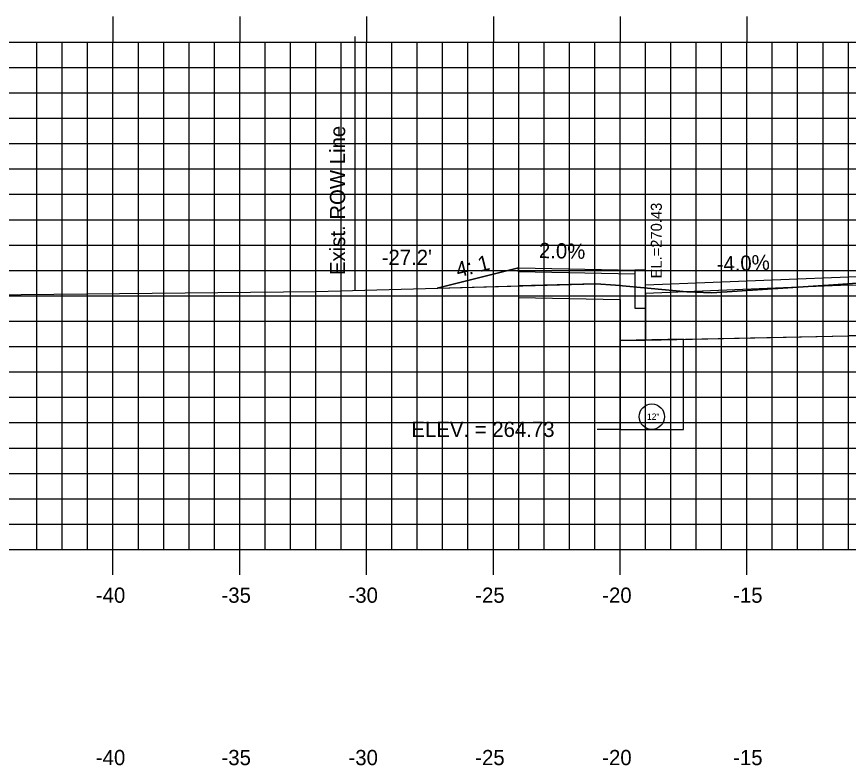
# Model space of a CAD drawing. Extents: x 854899 to 855069, y 366268 to 366378.
# Drawn here: x 854937.97 to 854970.77, y 366298.73 to 366328.24 of the extents above; entities that cross this region are included whole.
import ezdxf

# ---------------------------------------------------------------- set-up
doc = ezdxf.new("R2010")
doc.units = 0
for name, color, linetype in [('ANNOTATION', 7, 'Continuous'), ('D_Curb_Type_1_Lt', 7, 'Continuous'), ('D_Roadway_Centerline', 7, 'Continuous'), ('D_Roadway_Edge_Shoulder', 7, 'Continuous'), ('D_Roadway_FinishedGrade', 7, 'Continuous'), ('D_Roadway_Sidewalks_Paved', 7, 'Continuous'), ('D_Roadway_SubGrade', 7, 'Continuous'), ('D_Text_Standard', 7, 'Continuous'), ('E_ROW_Line', 7, 'Continuous'), ('H_V ANNOTATION', 7, 'Continuous'), ('JUNK COM EXC', 7, 'Continuous'), ('JUNK FILL', 7, 'Continuous'), ('junk strct exc', 7, 'Continuous'), ('MAJOR', 7, 'Continuous'), ('MINOR', 7, 'Continuous'), ('PDRAIN', 7, 'Continuous'), ('S_Roadway_Centerline', 7, 'Continuous')]:
    doc.layers.add(name, color=color, linetype=linetype)

msp = doc.modelspace()

# ---------------------------------------------------------------- linework, layer by layer
at = {"layer": 'D_Curb_Type_1_Lt'}
msp.add_lwpolyline([(854962.357, 366318.249), (854962.357, 366316.749), (854962.774, 366316.749), (854962.774, 366318.249)], close=True, dxfattribs=at)
at = {"layer": 'D_Roadway_Centerline'}
msp.add_lwpolyline([(854970.774, 366317.986), (854981.774, 366318.206), (854992.774, 366317.986)], dxfattribs=at)
at = {"layer": 'D_Roadway_Edge_Shoulder'}
msp.add_lwpolyline([(854962.774, 366317.666), (854970.774, 366317.986), (854981.774, 366318.206), (854992.774, 366317.986), (855000.774, 366317.665)], dxfattribs=at)
at = {"layer": 'D_Roadway_FinishedGrade'}
msp.add_line((854954.559, 366317.538), (854957.769, 366318.341), dxfattribs=at)
at = {"layer": 'D_Roadway_Sidewalks_Paved'}
msp.add_lwpolyline([(854957.769, 366318.341), (854962.357, 366318.249), (854962.357, 366318.082), (854957.769, 366318.174)], close=True, dxfattribs=at)
at = {"layer": 'D_Roadway_SubGrade'}
msp.add_lwpolyline([(854957.769, 366318.174), (854957.769, 366317.174), (854961.774, 366317.094), (854961.774, 366315.472), (854962.774, 366315.492)], dxfattribs=at)
for points in [[(854970.774, 366317.652), (854962.774, 366317.332), (854962.774, 366315.492), (854970.774, 366315.652)], [(854970.774, 366315.652), (854970.774, 366317.652), (854981.774, 366317.872), (854992.774, 366317.652), (854992.774, 366315.652), (854981.774, 366315.872)]]:
    msp.add_lwpolyline(points, close=True, dxfattribs=at)
at = {"layer": 'D_Text_Standard'}
msp.add_lwpolyline([(854961.774, 366311.971), (854961.543, 366311.971), (854960.863, 366311.971)], dxfattribs=at)
at = {"layer": 'E_ROW_Line'}
msp.add_line((854951.329, 366317.451), (854951.329, 366327.451), dxfattribs=at)
at = {"layer": 'JUNK COM EXC'}
msp.add_lwpolyline([(854971.488, 366317.76), (854970.188, 366317.674), (854965.385, 366317.346), (854964.403, 366317.388), (854961.589, 366317.66), (854960.814, 366317.707), (854957.769, 366317.625), (854957.769, 366317.174), (854961.774, 366317.094), (854961.774, 366315.472), (854970.774, 366315.652), (854981.774, 366315.872)], dxfattribs=at)
at = {"layer": 'JUNK FILL'}
msp.add_lwpolyline([(854957.774, 366317.625), (854957.774, 366318.341), (854957.769, 366318.341), (854954.559, 366317.538)], close=True, dxfattribs=at)
at = {"layer": 'junk strct exc'}
msp.add_lwpolyline([(854961.774, 366315.472), (854961.774, 366311.971), (854964.274, 366311.971), (854964.274, 366315.522)], close=True, dxfattribs=at)
at = {"layer": 'MAJOR'}
for p, q in [((854941.774, 366328.238), (854941.774, 366327.236)), ((854946.774, 366328.238), (854946.774, 366327.236)), ((854951.774, 366328.238), (854951.774, 366327.236)), ((854956.774, 366328.238), (854956.774, 366327.236)), ((854961.774, 366328.238), (854961.774, 366327.236)), ((854966.774, 366328.238), (854966.774, 366327.236)), ((854911.774, 366327.236), (855051.774, 366327.236)), ((854911.774, 366327.236), (855051.774, 366327.236)), ((854941.774, 366307.236), (854941.774, 366327.236)), ((854946.774, 366307.236), (854946.774, 366327.236)), ((854951.774, 366307.236), (854951.774, 366327.236)), ((854956.774, 366307.236), (854956.774, 366327.236)), ((854961.774, 366307.236), (854961.774, 366327.236)), ((854966.774, 366307.236), (854966.774, 366327.236)), ((854911.774, 366322.236), (855051.774, 366322.236)), ((854911.774, 366317.236), (855051.774, 366317.236)), ((854911.774, 366312.236), (855051.774, 366312.236)), ((854911.774, 366307.236), (855051.774, 366307.236)), ((854911.774, 366307.236), (855051.774, 366307.236)), ((854941.774, 366306.234), (854941.774, 366307.236)), ((854946.774, 366306.234), (854946.774, 366307.236)), ((854951.774, 366306.234), (854951.774, 366307.236)), ((854956.774, 366306.234), (854956.774, 366307.236)), ((854961.774, 366306.234), (854961.774, 366307.236)), ((854966.774, 366306.234), (854966.774, 366307.236))]:
    msp.add_line(p, q, dxfattribs=at)
at = {"layer": 'MINOR'}
for p, q in [((854938.774, 366307.236), (854938.774, 366327.236)), ((854939.774, 366307.236), (854939.774, 366327.236)), ((854940.774, 366307.236), (854940.774, 366327.236)), ((854942.774, 366307.236), (854942.774, 366327.236)), ((854943.774, 366307.236), (854943.774, 366327.236)), ((854944.774, 366307.236), (854944.774, 366327.236)), ((854945.774, 366307.236), (854945.774, 366327.236)), ((854947.774, 366307.236), (854947.774, 366327.236)), ((854948.774, 366307.236), (854948.774, 366327.236)), ((854949.774, 366307.236), (854949.774, 366327.236)), ((854950.774, 366307.236), (854950.774, 366327.236)), ((854952.774, 366307.236), (854952.774, 366327.236)), ((854953.774, 366307.236), (854953.774, 366327.236)), ((854954.774, 366307.236), (854954.774, 366327.236)), ((854955.774, 366307.236), (854955.774, 366327.236)), ((854957.774, 366307.236), (854957.774, 366327.236)), ((854958.774, 366307.236), (854958.774, 366327.236)), ((854959.774, 366307.236), (854959.774, 366327.236)), ((854960.774, 366307.236), (854960.774, 366327.236)), ((854962.774, 366307.236), (854962.774, 366327.236)), ((854963.774, 366307.236), (854963.774, 366327.236)), ((854964.774, 366307.236), (854964.774, 366327.236)), ((854965.774, 366307.236), (854965.774, 366327.236)), ((854967.774, 366307.236), (854967.774, 366327.236)), ((854968.774, 366307.236), (854968.774, 366327.236)), ((854969.774, 366307.236), (854969.774, 366327.236)), ((854970.774, 366307.236), (854970.774, 366327.236)), ((854911.774, 366326.236), (855051.774, 366326.236)), ((854911.774, 366325.236), (855051.774, 366325.236)), ((854911.774, 366324.236), (855051.774, 366324.236)), ((854911.774, 366323.236), (855051.774, 366323.236)), ((854911.774, 366321.236), (855051.774, 366321.236)), ((854911.774, 366320.236), (855051.774, 366320.236)), ((854911.774, 366319.236), (855051.774, 366319.236)), ((854911.774, 366318.236), (855051.774, 366318.236)), ((854911.774, 366316.236), (855051.774, 366316.236)), ((854911.774, 366315.236), (855051.774, 366315.236)), ((854911.774, 366314.236), (855051.774, 366314.236)), ((854911.774, 366313.236), (855051.774, 366313.236)), ((854911.774, 366311.236), (855051.774, 366311.236)), ((854911.774, 366310.236), (855051.774, 366310.236)), ((854911.774, 366309.236), (855051.774, 366309.236)), ((854911.774, 366308.236), (855051.774, 366308.236))]:
    msp.add_line(p, q, dxfattribs=at)
at = {"layer": 'PDRAIN'}
msp.add_lwpolyline([(854961.774, 366315.472), (854961.774, 366311.971), (854964.274, 366311.971), (854964.274, 366315.472)], dxfattribs=at)
msp.add_circle((854963.024, 366312.471), 0.5, dxfattribs=at)
at = {"layer": 'S_Roadway_Centerline'}
msp.add_lwpolyline([(854924.068, 366316.94), (854929.097, 366317.144), (854935.552, 366317.258), (854949.789, 366317.41), (854960.814, 366317.707), (854961.589, 366317.66), (854964.403, 366317.388), (854965.385, 366317.346), (854970.188, 366317.674), (854971.488, 366317.76), (854972.612, 366317.778), (854982.41, 366318.199), (854987.873, 366318.081), (854993.388, 366318.007), (854995.003, 366317.976), (854999.964, 366317.964), (855001.001, 366318.016), (855005.553, 366318.042), (855007.414, 366318.074), (855018.059, 366317.982)], dxfattribs=at)

# ---------------------------------------------------------------- texts
at = {"layer": 'ANNOTATION'}
for s, rotation, p in [('2.0%', 358.8542, (854958.567, 366318.725)), ('4: 1', 14.0362, (854955.379, 366317.952)), ('-4.0%', 2.2906, (854965.59, 366318.179))]:
    msp.add_text(s, height=0.6, rotation=rotation, dxfattribs=at).set_placement(p)
at = {"layer": 'D_Text_Standard'}
msp.add_text(' EL.=270.43', height=0.4335, rotation=90, dxfattribs=at).set_placement((854963.418, 366317.76))
for s, p in [("-27.2'", (854952.37, 366318.451)), ('ELEV. = 264.73', (854953.543, 366311.671))]:
    msp.add_text(s, height=0.6, dxfattribs=at).set_placement(p)
at = {"layer": 'E_ROW_Line'}
msp.add_text('Exist. ROW Line', height=0.6, rotation=90, dxfattribs=at).set_placement((854950.929, 366318.051))
at = {"layer": 'H_V ANNOTATION'}
for s, p in [('-40', (854941.1, 366305.136)), ('-35', (854946.054, 366305.136)), ('-30', (854951.062, 366305.136)), ('-25', (854956.06, 366305.136)), ('-20', (854961.068, 366305.136)), ('-15', (854966.231, 366305.136)), ('-40', (854941.1, 366298.736)), ('-35', (854946.054, 366298.736)), ('-30', (854951.062, 366298.736)), ('-25', (854956.06, 366298.736)), ('-20', (854961.068, 366298.736)), ('-15', (854966.231, 366298.736))]:
    msp.add_text(s, height=0.6, dxfattribs=at).set_placement(p)
at = {"layer": 'PDRAIN'}
msp.add_text('12"', height=0.25, dxfattribs=at).set_placement((854962.833, 366312.346))

doc.saveas('drawing.dxf')
